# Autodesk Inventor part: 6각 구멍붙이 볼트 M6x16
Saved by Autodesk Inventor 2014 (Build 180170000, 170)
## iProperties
Created: 2026-09
Part Number: 6각 구멍붙이 볼트 M6x16
Material: 일반
Document SubType Name: Modeling
Designer: dg
Density: 1 g/cm^3
Appearance: 기본값
Author: dg
Author: jhkim
Description: 6각머리 태핑 나사
Creation Date: 2026-08-26
Sending System: Autodesk Inventor 2027
Preprocessor: ST-DEVELOPER v20.1
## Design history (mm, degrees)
node "6각 구멍붙이 볼트 M6x161"
body "Solid1"
node "기준1"
